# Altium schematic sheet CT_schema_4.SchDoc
size 382 x 218 mm
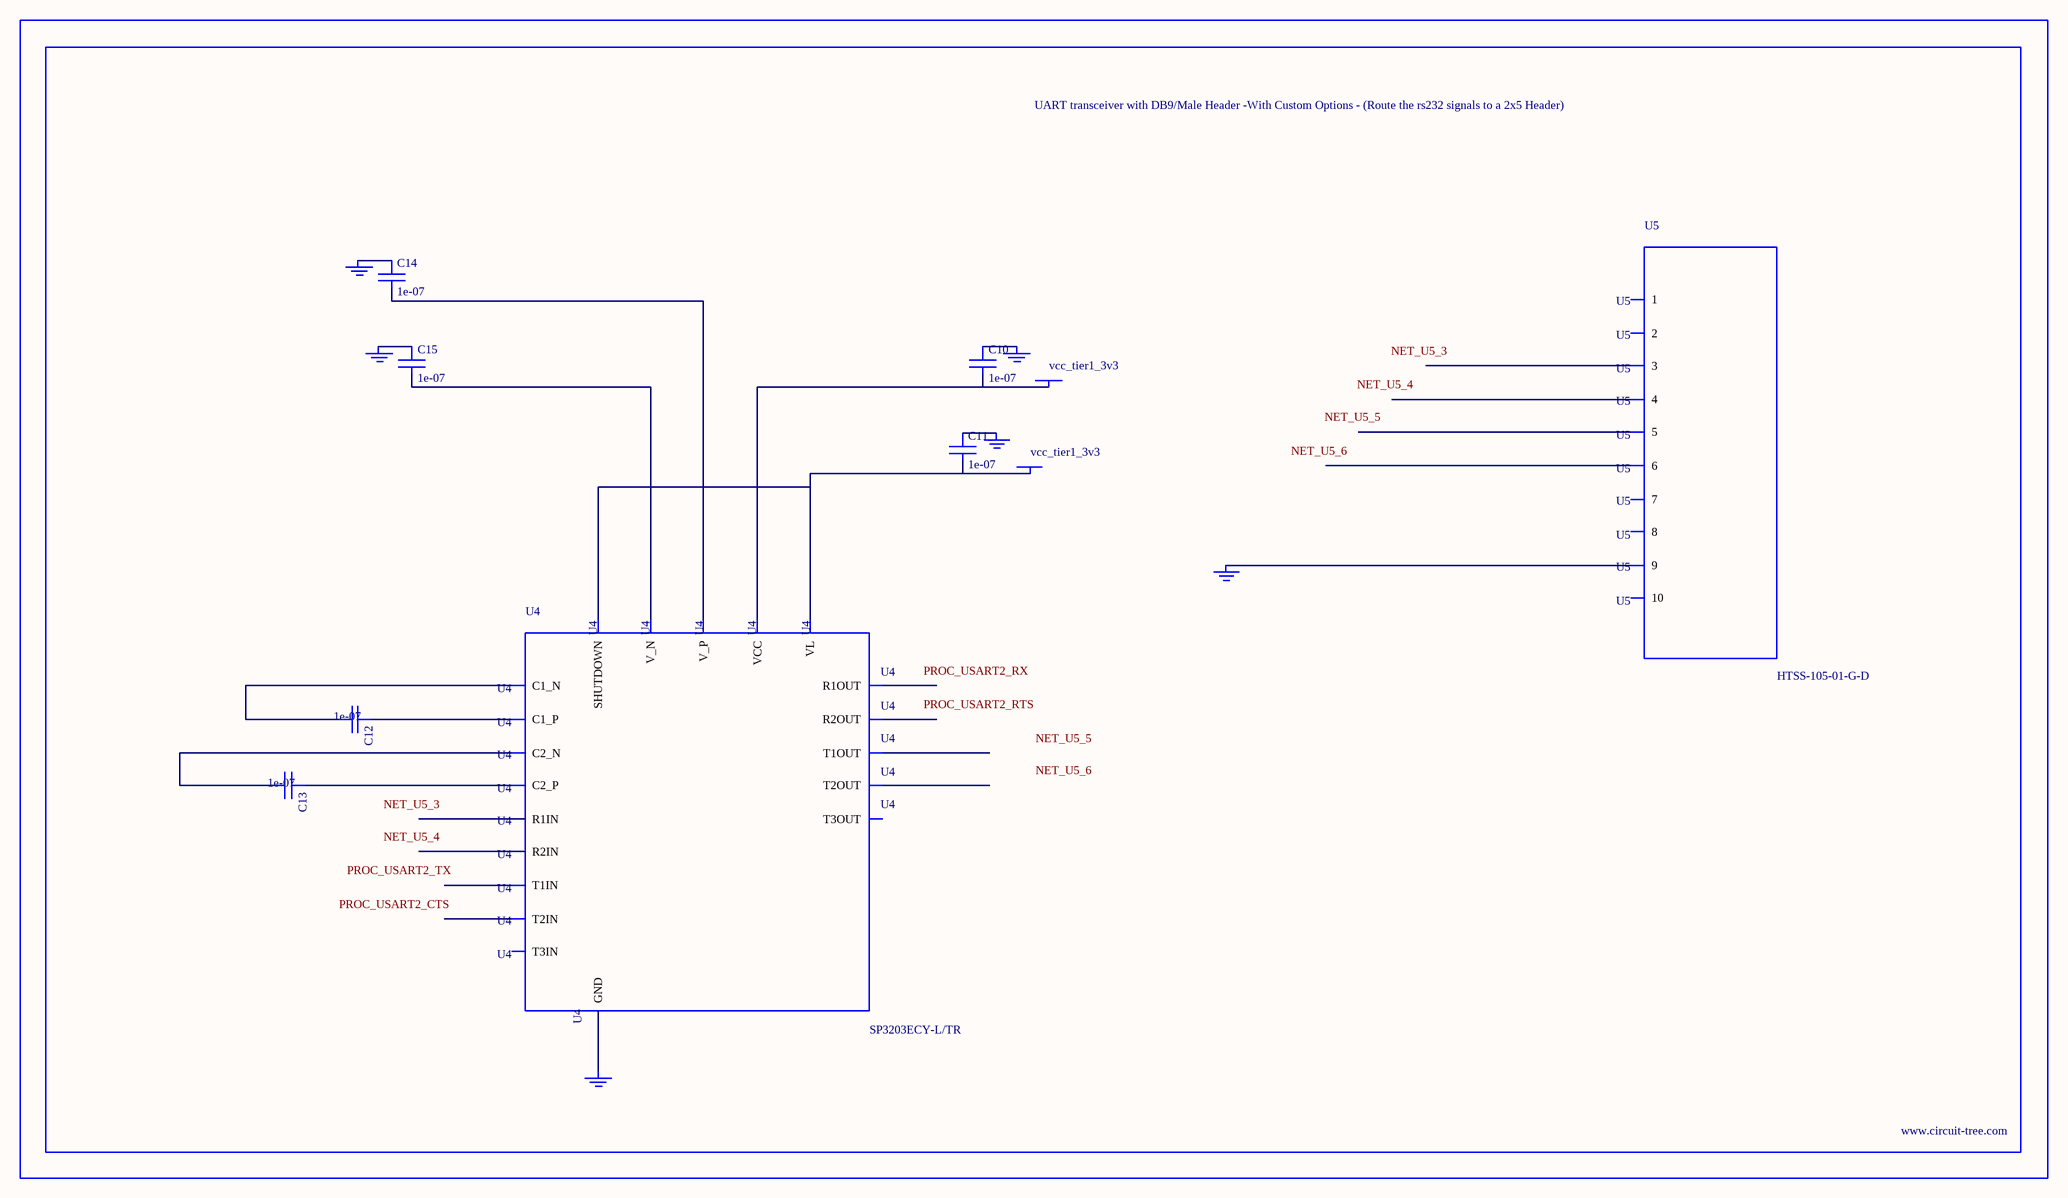
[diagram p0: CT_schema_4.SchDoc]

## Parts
BORDER3  (no value)
C10  1e-07  [C0402]
C11  1e-07  [C0402]
C12  1e-07  [C0402]
C13  1e-07  [C0402]
C14  1e-07  [C0402]
C15  1e-07  [C0402]
GND_INSTANCE_3_0  (no value)
GND_INSTANCE_3_1  (no value)
GND_INSTANCE_3_2  (no value)
GND_INSTANCE_3_3  (no value)
GND_INSTANCE_3_4  (no value)
GND_INSTANCE_3_5  (no value)
POWER_INSTANCE_3_0  vcc_tier1_3v3
POWER_INSTANCE_3_1  vcc_tier1_3v3
U4  SP3203ECY-L/TR  [TSSOP20-I]
U5  HTSS-105-01-G-D  [HTSS-105-01-G-D]

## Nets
NetC10_1: C10.1 GND_INSTANCE_3_3.0(GND)
NetC10_2: C10.2 POWER_INSTANCE_3_1.0(PWR) U4.19(VCC)
NetC11_1: C11.1 GND_INSTANCE_3_2.0(GND)
NetC11_2: C11.2 POWER_INSTANCE_3_0.0(PWR) U4.12(VL) U4.20(SHUTDOWN)
NetC12_1: C12.1 U4.1(C1_P)
NetC12_2: C12.2 U4.3(C1_N)
NetC13_1: C13.1 U4.4(C2_P)
NetC13_2: C13.2 U4.5(C2_N)
NetC14_1: C14.1 GND_INSTANCE_3_0.0(GND)
NetC14_2: C14.2 U4.2(V_P)
NetC15_1: C15.1 GND_INSTANCE_3_1.0(GND)
NetC15_2: C15.2 U4.6(V_N)
NetGND_INSTANCE_3_4_0: GND_INSTANCE_3_4.0(GND) U4.18(GND)
NetGND_INSTANCE_3_5_0: GND_INSTANCE_3_5.0(GND) U5.9

Not connected (* = marked no-connect by the designer): U4 7(T1IN) 8(T2IN) 9(T3IN) 10(R2OUT) 11(R1OUT) 13(R2IN) 14(R1IN) 15(T3OUT) 16(T2OUT) 17(T1OUT); U5 1 2 3 4 5 6 7 8 10

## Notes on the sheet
- Labels drawn without touching a wire or pin: NET_U5_3, NET_U5_4, NET_U5_5, NET_U5_6, PROC_USART2_CTS, PROC_USART2_RTS, PROC_USART2_RX, PROC_USART2_TX

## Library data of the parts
BORDER3 = BORDER_PAGE3
C10-C15 = C0402C104K3RACTU
GND_INSTANCE_3_0-GND_INSTANCE_3_5 = GND
POWER_INSTANCE_3_0 POWER_INSTANCE_3_1 = PWR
